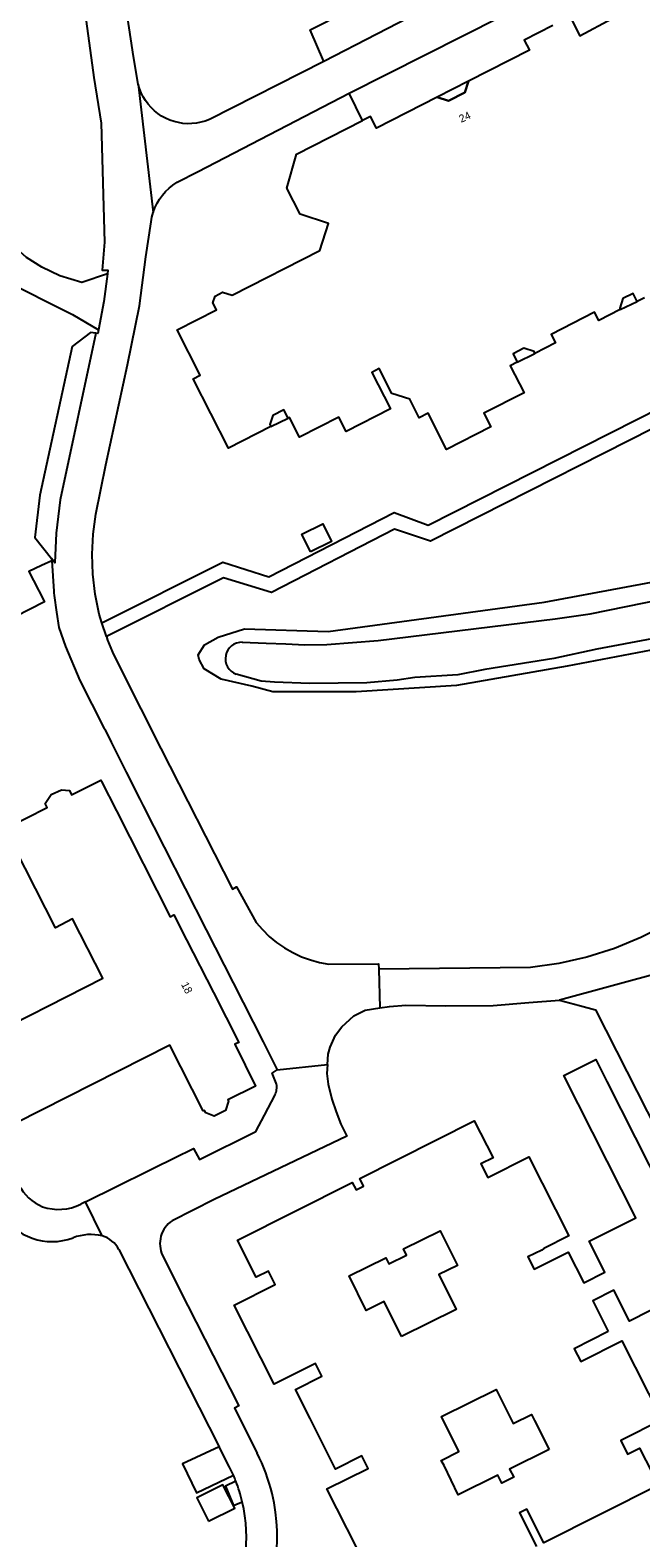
# Model space of a CAD drawing. Extents: x 158132 to 159658, y 385257 to 387209.
# Drawn here: x 158829.4 to 158908.4, y 386267.4 to 386462.6 of the extents above; entities that cross this region are included whole.
import ezdxf

# ---------------------------------------------------------------- set-up
doc = ezdxf.new("R2010")
doc.units = 0
for name, color, linetype in [('IMGEO_Gemengd_bos', 7, 'Continuous'), ('IMGEO_Groenvoorziening', 7, 'Continuous'), ('IMGEO_Meer_plas_ven_vijver', 7, 'Continuous'), ('IMGEO_Pand', 7, 'Continuous'), ('IMGEO_Pand_nummerreeks', 7, 'Continuous'), ('IMGEO_Pand_overbouw', 7, 'Continuous'), ('IMGEO_Parkeervlak_open', 7, 'Continuous'), ('IMGEO_Rijbaan_lokaal_gesloten', 7, 'Continuous'), ('IMGEO_Rijbaan_lokaal_open', 7, 'Continuous'), ('IMGEO_Voetpad_open', 7, 'Continuous')]:
    doc.layers.add(name, color=color, linetype=linetype)

msp = doc.modelspace()

# ---------------------------------------------------------------- linework, layer by layer
at = {"layer": 'IMGEO_Gemengd_bos'}
msp.add_lwpolyline([(158832.21, 386393.92), (158830.9, 386393.3), (158829.25, 386392.53), (158829.85, 386391.36), (158831.2, 386388.75), (158831.27, 386388.6), (158829.35, 386387.61), (158825.79, 386385.78), (158824.87, 386387.57), (158823.29, 386386.76)], dxfattribs=at)
at = {"layer": 'IMGEO_Groenvoorziening'}
msp.add_lwpolyline([(158915.17, 386383.39), (158898.87, 386380.25), (158884.56, 386377.76), (158871.59, 386376.94), (158860.79, 386376.94), (158858.11, 386377.66), (158854.14, 386378.57), (158851.91, 386379.92), (158851.28, 386381.12), (158851.17, 386381.72), (158851.95, 386383.03), (158853.75, 386384.02), (158857.13, 386385.08), (158867.95, 386384.76), (158895.9, 386388.53), (158917.19, 386392.52)], dxfattribs=at)
at = {"layer": 'IMGEO_Meer_plas_ven_vijver'}
for points in [[(158972.39, 386406.47), (158970.3, 386405.14), (158966.23, 386402.66), (158958.1, 386398.71), (158952.36, 386396.11), (158947.65, 386393.64), (158941.54, 386391.35), (158936.65, 386389.96), (158930.28, 386388.03), (158921.8, 386386.15), (158909.82, 386383.81), (158902.73, 386382.47), (158897.16, 386381.26), (158888.23, 386379.82), (158884.73, 386379.15), (158879.16, 386378.79), (158876.88, 386378.47), (158872.97, 386378.11), (158865.57, 386378.03), (158861.03, 386378.21), (158859.28, 386378.34), (158856.05, 386379.24)], [(158856.86, 386383.37), (158859.96, 386383.24), (158862.47, 386383.15), (158864.94, 386383.01), (158867.81, 386383.08), (158874.45, 386383.57), (158897.34, 386386.38), (158901.87, 386387.03), (158915.81, 386389.88)]]:
    msp.add_lwpolyline(points, dxfattribs=at)
msp.add_arc((158856.8, 386381.24), 2.13, 88.2549, 249.6006, dxfattribs=at)
at = {"layer": 'IMGEO_Pand'}
for points in [[(158897.04, 386463.21), (158893.3, 386461.3), (158893.99, 386460), (158886.12, 386455.98), (158885.64, 386454.51), (158883.54, 386453.43), (158882.08, 386453.91), (158874.22, 386449.9), (158873.45, 386451.41), (158872.42, 386450.88)], [(158899.25, 386464.34), (158900.51, 386461.85), (158904.68, 386464.1)], [(158908.88, 386427.95), (158907.94, 386427.47), (158907.4, 386428.52), (158906.08, 386427.84), (158905.67, 386426.6), (158905.75, 386426.44), (158902.96, 386425.01), (158902.42, 386426.07), (158896.82, 386423.21), (158897.38, 386422.12), (158894.69, 386420.76), (158894.59, 386420.98), (158893.27, 386421.41), (158891.88, 386420.7), (158892.43, 386419.61), (158891.51, 386419.14), (158893.3, 386415.64), (158888.12, 386413), (158889.02, 386411.24), (158883.28, 386408.3), (158880.88, 386413.01), (158879.75, 386412.43), (158878.53, 386414.82), (158876.22, 386415.57), (158874.58, 386418.78), (158873.62, 386418.28), (158876.02, 386413.58), (158870.29, 386410.66), (158869.36, 386412.48), (158864.27, 386409.89), (158862.96, 386412.46), (158862.78, 386412.36), (158862.23, 386413.44), (158860.82, 386412.72), (158860.44, 386411.55), (158860.57, 386411.3), (158855.08, 386408.49), (158850.51, 386417.45), (158851.43, 386417.92), (158848.43, 386423.8), (158853.51, 386426.39), (158853.05, 386427.28), (158853.34, 386428.18), (158854.31, 386428.67), (158855.54, 386428.28), (158866.88, 386434.06), (158868.01, 386437.56), (158864.33, 386438.76), (158862.6, 386442.15), (158863.89, 386446.53), (158872.42, 386450.88)], [(158865.7, 386395.08), (158864.58, 386397.37), (158867.27, 386398.69), (158868.39, 386396.4), (158865.7, 386395.08)], [(158822.36, 386331.49), (158838.82, 386339.86), (158834.91, 386347.54), (158832.68, 386346.41), (158826.18, 386359.19), (158831.64, 386361.96), (158831.38, 386362.48), (158832.15, 386363.66), (158833.46, 386364.27), (158834.5, 386364.17), (158834.78, 386363.61), (158838.56, 386365.53), (158838.65, 386365.34), (158840.59, 386361.52), (158847.51, 386347.83), (158848.02, 386348.08), (158849.65, 386344.86)], [(158849.65, 386344.86), (158853.12, 386338.01), (158856.39, 386331.57), (158855.89, 386331.32), (158858.56, 386325.9), (158854.98, 386324.14), (158855.08, 386323.94), (158854.7, 386322.77), (158853.22, 386322.01), (158852.13, 386322.44), (158851.96, 386322.77), (158851.8, 386322.69), (158847.47, 386331.21), (158827.59, 386321.1)], [(158872.99, 386263.49), (158867.81, 386273.78), (158873.14, 386276.41), (158872.32, 386278.03), (158868.93, 386276.33), (158867.06, 386280.04), (158865.62, 386282.89), (158863.73, 386286.62), (158867.14, 386288.35), (158866.31, 386290), (158860.98, 386287.32), (158855.82, 386297.55), (158861.12, 386300.22), (158860.24, 386301.97), (158858.67, 386301.18), (158856.26, 386305.98), (158871.07, 386313.45), (158871.57, 386312.47), (158872.55, 386312.97), (158872.05, 386313.95), (158886.87, 386321.42), (158889.29, 386316.63), (158887.72, 386315.84), (158888.62, 386314.06), (158893.93, 386316.74), (158899.08, 386306.53), (158895.84, 386304.9), (158895.6, 386304.68), (158893.78, 386303.82), (158894.6, 386302.2), (158899, 386304.42), (158901.02, 386300.42), (158903.77, 386301.81), (158901.74, 386305.82), (158907.76, 386308.86), (158898.46, 386327.27), (158902.57, 386329.34), (158904.01, 386326.5), (158911.32, 386312.01)], [(158877.46, 386293.48), (158875.2, 386298.02), (158872.9, 386296.88), (158870.68, 386301.33), (158875.42, 386303.68), (158875.81, 386302.89), (158878.11, 386304.04), (158877.72, 386304.83), (158882.46, 386307.19), (158884.7, 386302.69), (158882.29, 386301.5), (158884.53, 386297), (158877.46, 386293.48)], [(158912.3, 386298.2), (158906.93, 386295.47), (158904.9, 386299.49), (158902.2, 386298.13), (158904.2, 386294.12)], [(158904.2, 386294.12), (158899.8, 386291.9), (158900.63, 386290.25), (158905.94, 386292.93), (158911.11, 386282.69), (158905.8, 386280.01), (158906.68, 386278.26), (158908.25, 386279.05), (158910.67, 386274.26), (158895.87, 386266.79), (158893.68, 386271.15), (158892.7, 386270.65), (158894.89, 386266.3)], [(158896.57, 386278.87), (158891.44, 386276.31), (158891.96, 386275.27), (158890.44, 386274.51), (158889.92, 386275.55), (158884.79, 386273), (158882.96, 386276.78), (158882.59, 386277.46), (158884.88, 386278.6), (158882.62, 386283.13), (158889.68, 386286.65), (158891.89, 386282.22), (158894.28, 386283.4), (158894.65, 386282.6), (158896.57, 386278.87)], [(158852.49, 386269.57), (158855.89, 386271.28), (158854.36, 386274.31), (158850.96, 386272.6), (158852.49, 386269.57)]]:
    msp.add_lwpolyline(points, dxfattribs=at)
at = {"layer": 'IMGEO_Pand_overbouw'}
for points in [[(158882.08, 386453.91), (158883.54, 386453.43), (158885.64, 386454.51), (158886.12, 386455.98)], [(158905.75, 386426.44), (158907.94, 386427.47), (158907.4, 386428.52), (158906.08, 386427.84), (158905.67, 386426.6)], [(158892.43, 386419.61), (158894.69, 386420.76), (158894.59, 386420.98), (158893.27, 386421.41), (158891.88, 386420.7)], [(158862.78, 386412.36), (158862.23, 386413.44), (158860.82, 386412.72), (158860.44, 386411.55), (158860.57, 386411.3)]]:
    msp.add_lwpolyline(points, close=True, dxfattribs=at)
at = {"layer": 'IMGEO_Parkeervlak_open'}
for points in [[(158867.42, 386458.54), (158865.63, 386462.64), (158879.14, 386469.5)], [(158837.9, 386423.36), (158837.21, 386423.46), (158834.87, 386421.66), (158830.69, 386402.4), (158830.01, 386396.92), (158832.19, 386394.2)]]:
    msp.add_lwpolyline(points, dxfattribs=at)
at = {"layer": 'IMGEO_Rijbaan_lokaal_gesloten'}
for points in [[(158843.41, 386455.61), (158842.78, 386459.2), (158837.05, 386497.21), (158835.49, 386508.5), (158835.27, 386510.61), (158835.89, 386510.6), (158835.86, 386511.86), (158835.93, 386513.11), (158836.13, 386514.35), (158836.44, 386515.56), (158836.97, 386517.36), (158837.64, 386519.11), (158838.45, 386520.8), (158838.48, 386520.84), (158839.1, 386521.75), (158839.77, 386522.69), (158840.46, 386523.62), (158840.95, 386523.82), (158841.45, 386523.98), (158841.97, 386524.09), (158842.49, 386524.16), (158842.5, 386524.75)], [(158833.28, 386486.8), (158833.34, 386486.39), (158836.52, 386464.72), (158837.65, 386456.47), (158838.6, 386450.54), (158839.04, 386435.13), (158838.72, 386431.53), (158839.48, 386431.51), (158839.41, 386431.05)], [(158881.1, 386465.62), (158867.42, 386458.54)], [(158870.68, 386454.45), (158895.22, 386466.88)], [(158867.42, 386458.54), (158852.6, 386451.04), (158852.05, 386450.83), (158851.49, 386450.67), (158850.92, 386450.56), (158850.34, 386450.5), (158849.75, 386450.49), (158849.17, 386450.53), (158848.6, 386450.62), (158848.03, 386450.76), (158847.48, 386450.95), (158846.94, 386451.19), (158846.43, 386451.47), (158845.95, 386451.8), (158845.49, 386452.16), (158845.07, 386452.57), (158844.69, 386453.01), (158844.35, 386453.48), (158844.04, 386453.98), (158843.78, 386454.5), (158843.57, 386455.05), (158843.41, 386455.61)], [(158843.41, 386455.61), (158845.33, 386439.01)], [(158845.33, 386439.01), (158845.55, 386439.6), (158845.83, 386440.18), (158846.15, 386440.72), (158846.52, 386441.24), (158846.94, 386441.71), (158847.4, 386442.15), (158847.89, 386442.55), (158848.42, 386442.9), (158851.17, 386444.29), (158870.68, 386454.45)], [(158838.71, 386385.88), (158838.34, 386387.01), (158837.84, 386389.57), (158837.54, 386392.16), (158837.46, 386394.77), (158837.59, 386397.37), (158837.93, 386399.96), (158839.23, 386406.31), (158842.03, 386419.28), (158843.56, 386426.89), (158844.39, 386433.26), (158845.06, 386437.77), (158845.17, 386438.4), (158845.33, 386439.01)], [(158839.41, 386431.05), (158838.94, 386427.47), (158838.25, 386423.8)], [(158837.9, 386423.36), (158833.29, 386401.81), (158832.77, 386397.48), (158832.62, 386393.66), (158832.19, 386394.2)], [(158838.25, 386423.8), (158838.16, 386423.33), (158837.9, 386423.36)], [(158832.19, 386394.2), (158832.21, 386393.92)], [(158832.21, 386393.92), (158832.47, 386389.96), (158832.49, 386389.74), (158832.54, 386389.42), (158832.85, 386387.27), (158833.15, 386385.29), (158833.99, 386382.82), (158835.85, 386378.43), (158838.97, 386372.29), (158839.06, 386372.12), (158839.9, 386370.44), (158841.85, 386366.55), (158843.61, 386363.03), (158844.05, 386362.17), (158852.18, 386346.15), (158855.66, 386339.29), (158859.55, 386331.62), (158861.38, 386328.03)], [(159004.59, 386393.75), (158971.38, 386376.95), (158932.17, 386357.09), (158908.42, 386345.13), (158904.98, 386343.72), (158901.43, 386342.6), (158897.8, 386341.78), (158894.12, 386341.27), (158874.52, 386341.06)], [(158839.29, 386384.11), (158838.71, 386385.88)], [(158839.29, 386384.11), (158839.44, 386383.64), (158840.07, 386382.07), (158841.16, 386379.89), (158846.33, 386369.6), (158855.6, 386351.4), (158856.09, 386351.68), (158858.67, 386347.1), (158859.47, 386346.16), (158860.35, 386345.29), (158861.29, 386344.5), (158862.31, 386343.8), (158863.38, 386343.18), (158864.5, 386342.66), (158865.66, 386342.24), (158866.85, 386341.92), (158868.06, 386341.71), (158874.49, 386341.73), (158874.52, 386341.06)], [(158874.52, 386341.06), (158874.63, 386336.02)], [(158911.49, 386340.74), (158897.88, 386337.03)], [(158874.63, 386336.02), (158875.9, 386336.2), (158878.01, 386336.4), (158883.12, 386336.28), (158889.3, 386336.35), (158893.94, 386336.71), (158897.88, 386337.03)], [(158897.88, 386337.03), (158900.47, 386336.33), (158902.56, 386335.77), (158906.58, 386327.8), (158909.22, 386322.6), (158911.89, 386317.33), (158913.92, 386313.34), (158913.36, 386313.05), (158913.89, 386311.97), (158914.23, 386312.13), (158931.06, 386279.11), (158931.65, 386277.95), (158933.07, 386275.16)], [(158867.89, 386328.69), (158867.97, 386330.02), (158868.21, 386330.93), (158868.92, 386332.5), (158869.74, 386333.57), (158871.29, 386335), (158872.73, 386335.75), (158874.63, 386336.02)], [(158867.89, 386328.69), (158867.81, 386327.54), (158867.97, 386326.16), (158868.45, 386324.2), (158869, 386322.59), (158869.61, 386320.99), (158870.37, 386319.43), (158853.2, 386311.22), (158847.78, 386308.48), (158847.53, 386308.29), (158847.29, 386308.08), (158847.08, 386307.85), (158846.88, 386307.6), (158846.71, 386307.34), (158846.56, 386307.06), (158846.43, 386306.76), (158846.34, 386306.46), (158846.27, 386306.15), (158846.22, 386305.84), (158846.21, 386305.52), (158846.22, 386305.2), (158846.26, 386304.89), (158846.33, 386304.58), (158846.42, 386304.28), (158848.71, 386299.65), (158856.41, 386284.5), (158855.85, 386284.21), (158858.79, 386278.39)], [(158861.38, 386328.03), (158867.89, 386328.69)], [(158836.56, 386310.91), (158848.8, 386316.98), (158849.85, 386317.5), (158850.54, 386317.85), (158851.32, 386316.42), (158858.61, 386320.03), (158859.72, 386322.15), (158861.09, 386324.79), (158861.16, 386324.95), (158861.22, 386325.11), (158861.27, 386325.28), (158861.3, 386325.45), (158861.32, 386325.62), (158861.32, 386325.79), (158861.31, 386325.97), (158861.28, 386326.14), (158861.24, 386326.3), (158860.71, 386327.59), (158861.38, 386328.03)], [(158836.56, 386310.91), (158835.97, 386310.61)], [(158838.74, 386306.51), (158836.56, 386310.91)], [(158840.91, 386304.74), (158853.88, 386279.22)], [(158855.22, 386276.57), (158853.88, 386279.22)]]:
    msp.add_lwpolyline(points, dxfattribs=at)
for centre, radius, start, end in [((158833.58, 386316.16), 6.41, 208.1389, 246.3094), ((158832.26, 386313.6), 7.82, 211.1443, 290.2723), ((158833.1, 386316.54), 6.59, 251.4809, 295.8313), ((158837.23, 386300.47), 6.22, 75.9296, 111.2949), ((158837.79, 386303.13), 3.51, 27.4626, 74.4113), ((158837.25, 386267.5), 24.13, 13.5473, 26.8141), ((158836.32, 386267), 21.18, 23.7392, 26.8538), ((158838.09, 386267.81), 19.24, 21.1841, 23.6514), ((158837.37, 386267.51), 20.02, 13.2204, 21.2612), ((158837.39, 386267.51), 20, 331.0331, 13.2089), ((158837.3, 386267.52), 24.08, 327.6583, 13.5366)]:
    msp.add_arc(centre, radius, start, end, dxfattribs=at)
at = {"layer": 'IMGEO_Rijbaan_lokaal_open'}
for points in [[(158839.41, 386431.05), (158836.12, 386429.94), (158833.25, 386430.8), (158830.92, 386431.92), (158828.94, 386433.18), (158826.15, 386435.66), (158824.34, 386437.85), (158821.72, 386442.65), (158819.81, 386446.38), (158820.85, 386446.91), (158819.8, 386448.9)], [(158825.73, 386430.42), (158834.9, 386425.77), (158838.25, 386423.8)]]:
    msp.add_lwpolyline(points, dxfattribs=at)
at = {"layer": 'IMGEO_Voetpad_open'}
for points in [[(158872.42, 386450.88), (158870.68, 386454.45)], [(158838.71, 386385.88), (158854.35, 386393.71), (158860.27, 386391.85), (158876.51, 386400.14), (158880.9, 386398.53), (158951.46, 386434.27), (158954.45, 386433.39), (158968.14, 386440.2)], [(158969.75, 386438.88), (158954.64, 386431.27), (158951.64, 386432.17), (158881.22, 386396.45), (158876.53, 386397.99), (158860.64, 386389.79), (158854.42, 386391.72), (158839.29, 386384.11)], [(158853.88, 386279.22), (158849.14, 386277.02), (158850.93, 386273.25), (158855.71, 386275.53)], [(158856.03, 386274.77), (158854.69, 386274.1), (158855.74, 386271.61), (158856.86, 386272.09)]]:
    msp.add_lwpolyline(points, dxfattribs=at)

# ---------------------------------------------------------------- texts
at = {"layer": 'IMGEO_Pand_nummerreeks'}
for s, rotation, p in [('24', 25.3305, (158885.18, 386450.59)), ('18', 296.8543, (158848.91, 386339.08))]:
    msp.add_text(s, height=1, rotation=rotation, dxfattribs=at).set_placement(p)

doc.saveas('drawing.dxf')
